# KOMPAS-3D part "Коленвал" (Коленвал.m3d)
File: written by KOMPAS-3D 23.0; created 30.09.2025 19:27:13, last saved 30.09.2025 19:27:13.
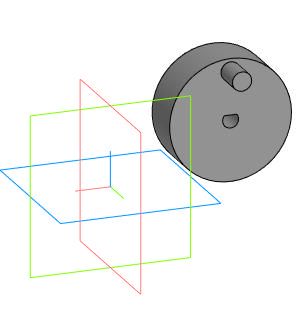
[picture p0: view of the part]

Document properties: Автор: Inspektor_Kot; Полное имя файла: I:\Autodesk Inventor Projects\ИМ-ИТ ЦД\Вариант 6\Коленвал.m3d

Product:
- Part/product: Коленвал

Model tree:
1. Эскиз:1  (with: Операция без истории:1)  (labels: Движок 12В; I:\Autodesk Inventor Projects\ИМ-ИТ ЦД\Вариант 6\Шатун.a3d)
2. Элемент выдавливания:1
     Расстояние 1 = 14.5
3. Эскиз:2  (with: Элемент выдавливания:1)
4. Элемент выдавливания:2
     Расстояние 2 = 24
